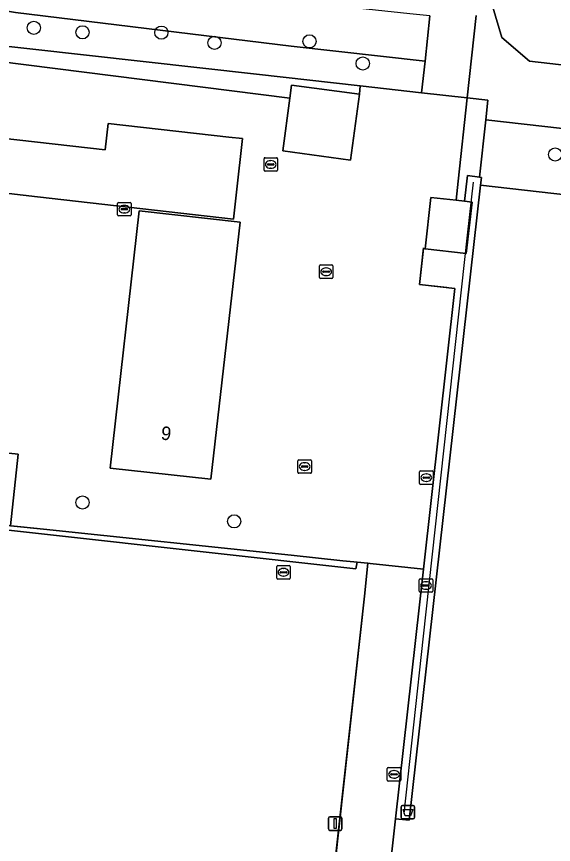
# Model space of a CAD drawing. Extents: x 162510 to 163918, y 388494 to 389774.
# Drawn here: x 162979.6 to 163019.4, y 388786.2 to 388847.5 of the extents above; entities that cross this region are included whole.
import ezdxf

# ---------------------------------------------------------------- set-up
doc = ezdxf.new("R2010")
doc.units = 0
for name, color, linetype in [('IMGEO_Afvalbak', 7, 'Continuous'), ('IMGEO_Boom', 7, 'Continuous'), ('IMGEO_Grasland_agrarisch', 7, 'Continuous'), ('IMGEO_Grasland_overig', 7, 'Continuous'), ('IMGEO_Groenvoorziening', 7, 'Continuous'), ('IMGEO_Hek', 7, 'Continuous'), ('IMGEO_Houtwal', 7, 'Continuous'), ('IMGEO_Kolk', 7, 'Continuous'), ('IMGEO_Lichtmast', 7, 'Continuous'), ('IMGEO_Loofbos', 7, 'Continuous'), ('IMGEO_Pand', 7, 'Continuous'), ('IMGEO_Pand_nummerreeks', 7, 'Continuous'), ('IMGEO_Rijbaan_lokaal_open', 7, 'Continuous'), ('IMGEO_Rioolput', 7, 'Continuous'), ('IMGEO_Terreindeel_open', 7, 'Continuous'), ('IMGEO_Voetpad_onverhard', 7, 'Continuous'), ('IMGEO_Voetpad_open', 7, 'Continuous')]:
    doc.layers.add(name, color=color, linetype=linetype)

msp = doc.modelspace()

# ---------------------------------------------------------------- linework, layer by layer
at = {"layer": 'IMGEO_Afvalbak'}
for p, q in [((163008.161, 388788.14), (163008.161, 388788.94)), ((163008.161, 388788.94), (163008.161, 388788.14)), ((163008.261, 388789.04), (163009.051, 388789.04)), ((163009.051, 388789.04), (163008.261, 388789.04)), ((163009.151, 388788.94), (163009.151, 388788.14)), ((163009.151, 388788.14), (163009.151, 388788.94)), ((163009.051, 388788.04), (163008.261, 388788.04)), ((163008.261, 388788.04), (163009.051, 388788.04))]:
    msp.add_line(p, q, dxfattribs=at)
msp.add_lwpolyline([(163008.304, 388788.754), (163009.008, 388788.754), (163008.859, 388788.284), (163008.453, 388788.284), (163008.304, 388788.754)], dxfattribs=at)
for centre, start, end in [((163008.261, 388788.94), 90, 180), ((163008.261, 388788.94), 90, 180), ((163009.051, 388788.94), 0, 90), ((163009.051, 388788.94), 360, 90), ((163008.261, 388788.14), 180, 270), ((163008.261, 388788.14), 180, 270), ((163009.051, 388788.14), 270, 0), ((163009.051, 388788.14), 270, 0)]:
    msp.add_arc(centre, 0.1, start, end, dxfattribs=at)
at = {"layer": 'IMGEO_Boom'}
for centre in [(162980.923, 388846.675), (162984.528, 388846.341), (162990.381, 388846.315), (162994.318, 388845.562), (163001.362, 388845.667), (163005.307, 388844.026), (163019.568, 388837.287), (162984.528, 388811.498), (162995.773, 388810.096)]:
    msp.add_circle(centre, 0.489, dxfattribs=at)
at = {"layer": 'IMGEO_Grasland_agrarisch'}
msp.add_lwpolyline([(163027.072, 388891.477), (162993.528, 388895.29), (162992.032, 388880.136), (162993.087, 388878.077), (162993.953, 388876.52), (163000.591, 388868.452), (163013.337, 388853.633), (163015.612, 388845.965), (163017.673, 388844.204), (163104.81, 388834.206)], dxfattribs=at)
at = {"layer": 'IMGEO_Grasland_overig'}
msp.add_lwpolyline([(162774.839, 389000), (162777.135, 388956.129), (162778.831, 388954.663), (162779.955, 388953.691), (162780.453, 388946.501), (162790.547, 388873.945), (162879.792, 388864.663), (162979.559, 388847.808), (163000, 388845.318), (163009.923, 388844.191), (163010.289, 388847.555), (163008.804, 388847.711), (163000, 388848.639), (162973.828, 388852.079)], dxfattribs=at)
at = {"layer": 'IMGEO_Groenvoorziening'}
for points in [[(162981.636, 388809.507), (162979.197, 388809.763), (162972.476, 388810.468), (162868.327, 388822.062), (162872.602, 388861.371), (162799.078, 388869.538), (162799.041, 388869.269), (162871.559, 388861.161), (162872.238, 388860.105), (162867.846, 388821.822), (163004.798, 388806.577), (163004.9, 388807.069), (163004.637, 388807.096), (163003.824, 388807.181), (163000, 388807.582)], [(163119.889, 388822.986), (163014.044, 388835.011), (163008.756, 388787.944), (163007.737, 388788.054), (163003.56, 388750.47), (163004.604, 388750.347), (163004.147, 388746.215), (163003.255, 388738.16), (163001.722, 388724.299), (163001.611, 388723.299), (163001.32, 388723.33), (163000, 388710.953), (162999.089, 388702.41), (163000, 388702.312), (163104.95, 388690.968), (163111.679, 388750)]]:
    msp.add_lwpolyline(points, close=True, dxfattribs=at)
for points in [[(163000, 388755.61), (163005.427, 388804.551), (163005.689, 388806.988), (163004.9, 388807.069), (163004.798, 388806.577), (162867.846, 388821.822), (162872.238, 388860.105), (162871.559, 388861.161), (162799.041, 388869.269), (162798.244, 388863.435), (162742.465, 388857.66)], [(162868.327, 388822.062), (162972.476, 388810.468), (162979.197, 388809.763), (162979.755, 388815.086), (162971.737, 388815.952), (162971.669, 388815.631), (162960.815, 388816.865), (162949.322, 388818.171), (162949.815, 388823.253), (162949.289, 388823.333), (162949.563, 388825.794), (162943.388, 388826.504), (162944.053, 388832.282), (162942.876, 388832.417), (162944.568, 388847.133), (162951.853, 388846.32), (162951.985, 388847.505), (162999.905, 388841.465), (163000.034, 388842.427), (163005.06, 388841.755), (163005.122, 388842.376), (162997.437, 388843.236), (162976.404, 388845.59), (162888.818, 388859.069)]]:
    msp.add_lwpolyline(points, dxfattribs=at)
at = {"layer": 'IMGEO_Hek'}
for points in [[(163000, 388845.318), (162979.559, 388847.808), (162879.792, 388864.663)], [(162888.818, 388859.069), (162976.404, 388845.59), (162997.437, 388843.236)], [(163000, 388845.318), (163009.923, 388844.191)], [(162997.437, 388843.236), (163005.122, 388842.376), (163009.67, 388841.867)], [(162999.381, 388837.545), (162999.905, 388841.465), (163000.034, 388842.427)], [(163000.034, 388842.427), (163005.06, 388841.755)], [(163005.06, 388841.755), (163004.407, 388836.873)], [(163009.67, 388841.867), (163013.046, 388841.484)], [(163013.046, 388841.484), (163014.583, 388841.309), (163014.422, 388839.85)], [(163014.422, 388839.85), (163013.951, 388835.598)], [(163004.407, 388836.873), (162999.381, 388837.545)], [(163008.368, 388788.444), (163009.813, 388801.599), (163013.076, 388831.3), (163013.51, 388835.244)], [(163014.044, 388835.011), (163119.889, 388822.986), (163111.679, 388750)], [(163011.529, 388827.418), (163009.522, 388827.661), (163009.819, 388830.371)], [(162981.636, 388809.507), (162972.476, 388810.468)], [(163003.824, 388807.181), (163000, 388807.582), (162981.636, 388809.507)], [(163005.689, 388806.988), (163005.427, 388804.551), (162995.492, 388714.399)], [(163004.637, 388807.096), (163003.824, 388807.181)], [(163004.637, 388807.096), (163004.9, 388807.069)], [(163004.9, 388807.069), (163005.689, 388806.988), (163005.868, 388806.969)], [(163009.285, 388806.615), (163005.868, 388806.969)]]:
    msp.add_lwpolyline(points, dxfattribs=at)
at = {"layer": 'IMGEO_Houtwal'}
msp.add_lwpolyline([(162879.792, 388864.663), (162790.547, 388873.945), (162789.747, 388873.272), (162788.349, 388873.034), (162788.737, 388870.608), (162799.078, 388869.538), (162872.602, 388861.371), (162879.687, 388860.474), (162888.818, 388859.069), (162976.404, 388845.59), (162997.437, 388843.236), (163005.122, 388842.376), (163009.67, 388841.867), (163009.923, 388844.191), (163000, 388845.318), (162979.559, 388847.808)], close=True, dxfattribs=at)
at = {"layer": 'IMGEO_Kolk'}
for p, q in [((162998.062, 388837.048), (162998.914, 388837.048)), ((162997.987, 388836.122), (162997.987, 388836.974)), ((162998.246, 388836.542), (162998.246, 388836.554)), ((162998.684, 388836.505), (162998.286, 388836.505)), ((162998.289, 388836.591), (162998.687, 388836.591)), ((162998.475, 388836.828), (162998.5, 388836.828)), ((162998.73, 388836.554), (162998.73, 388836.542)), ((162998.988, 388836.974), (162998.988, 388836.122)), ((162998.914, 388836.048), (162998.062, 388836.048)), ((162998.498, 388836.268), (162998.473, 388836.268)), ((162987.135, 388832.805), (162987.135, 388833.657)), ((162987.21, 388833.731), (162988.062, 388833.731)), ((162987.623, 388833.511), (162987.648, 388833.511)), ((162988.136, 388833.657), (162988.136, 388832.805)), ((162988.062, 388832.731), (162987.21, 388832.731)), ((162987.394, 388833.225), (162987.394, 388833.237)), ((162987.832, 388833.188), (162987.434, 388833.188)), ((162987.437, 388833.274), (162987.835, 388833.274)), ((162987.646, 388832.951), (162987.621, 388832.951)), ((162987.878, 388833.237), (162987.878, 388833.225)), ((163002.092, 388828.171), (163002.092, 388829.023)), ((163002.167, 388829.097), (163003.019, 388829.097)), ((163003.093, 388829.023), (163003.093, 388828.171)), ((163002.351, 388828.591), (163002.351, 388828.603)), ((163002.789, 388828.554), (163002.391, 388828.554)), ((163002.394, 388828.64), (163002.792, 388828.64)), ((163002.58, 388828.877), (163002.605, 388828.877)), ((163002.835, 388828.603), (163002.835, 388828.591)), ((163003.019, 388828.097), (163002.167, 388828.097)), ((163002.603, 388828.317), (163002.578, 388828.317)), ((163000.505, 388813.732), (163000.505, 388814.584)), ((163000.58, 388814.658), (163001.432, 388814.658)), ((163000.993, 388814.438), (163001.018, 388814.438)), ((163001.506, 388814.584), (163001.506, 388813.732)), ((163000.764, 388814.152), (163000.764, 388814.164)), ((163001.202, 388814.115), (163000.804, 388814.115)), ((163000.807, 388814.201), (163001.205, 388814.201)), ((163001.016, 388813.878), (163000.991, 388813.878)), ((163001.248, 388814.164), (163001.248, 388814.152)), ((163009.516, 388812.91), (163009.516, 388813.762)), ((163009.591, 388813.836), (163010.443, 388813.836)), ((163010.517, 388813.762), (163010.517, 388812.91)), ((163001.432, 388813.658), (163000.58, 388813.658)), ((163009.775, 388813.33), (163009.775, 388813.342)), ((163010.213, 388813.293), (163009.815, 388813.293)), ((163009.818, 388813.379), (163010.216, 388813.379)), ((163010.004, 388813.616), (163010.029, 388813.616)), ((163010.259, 388813.342), (163010.259, 388813.33)), ((163010.443, 388812.836), (163009.591, 388812.836)), ((163010.027, 388813.056), (163010.002, 388813.056)), ((163007.128, 388790.922), (163007.128, 388791.774)), ((163007.203, 388791.848), (163008.055, 388791.848)), ((163007.616, 388791.628), (163007.641, 388791.628)), ((163008.129, 388791.774), (163008.129, 388790.922)), ((163007.387, 388791.342), (163007.387, 388791.354)), ((163007.825, 388791.305), (163007.427, 388791.305)), ((163007.43, 388791.391), (163007.828, 388791.391)), ((163007.639, 388791.068), (163007.614, 388791.068)), ((163007.871, 388791.354), (163007.871, 388791.342)), ((163008.055, 388790.848), (163007.203, 388790.848))]:
    msp.add_line(p, q, dxfattribs=at)
for points in [[(162998.062, 388837.048), (162998.914, 388837.048)], [(162997.987, 388836.122), (162997.987, 388836.974)], [(162998.988, 388836.974), (162998.988, 388836.122)], [(162998.914, 388836.048), (162998.062, 388836.048)], [(162987.135, 388832.805), (162987.135, 388833.657)], [(162987.21, 388833.731), (162988.062, 388833.731)], [(162988.136, 388833.657), (162988.136, 388832.805)], [(162988.062, 388832.731), (162987.21, 388832.731)], [(163002.092, 388828.171), (163002.092, 388829.023)], [(163002.167, 388829.097), (163003.019, 388829.097)], [(163003.093, 388829.023), (163003.093, 388828.171)], [(163003.019, 388828.097), (163002.167, 388828.097)], [(163000.505, 388813.732), (163000.505, 388814.584)], [(163000.58, 388814.658), (163001.432, 388814.658)], [(163001.506, 388814.584), (163001.506, 388813.732)], [(163009.516, 388812.91), (163009.516, 388813.762)], [(163009.591, 388813.836), (163010.443, 388813.836)], [(163010.517, 388813.762), (163010.517, 388812.91)], [(163001.432, 388813.658), (163000.58, 388813.658)], [(163010.443, 388812.836), (163009.591, 388812.836)], [(163007.128, 388790.922), (163007.128, 388791.774)], [(163007.203, 388791.848), (163008.055, 388791.848)], [(163008.129, 388791.774), (163008.129, 388790.922)], [(163008.055, 388790.848), (163007.203, 388790.848)]]:
    msp.add_lwpolyline(points, dxfattribs=at)
for centre, radius, start, end in [((162998.064, 388836.972), 0.0765, 91.55205, 178.44795), ((162998.064, 388836.972), 0.0765, 91.55205, 178.44795), ((162998.912, 388836.972), 0.0765, 1.55205, 88.44795), ((162998.912, 388836.972), 0.0765, 1.55205, 88.44795), ((162998.286, 388836.551), 0.0403, 85.87752, 175.75265), ((162998.283, 388836.541), 0.0366, 178.93798, 274.71019), ((162998.687, 388836.548), 0.043, 264.86636, 352.45326), ((162998.691, 388836.553), 0.0386, 1.73085, 96.63898), ((162998.064, 388836.124), 0.0765, 181.55205, 268.44795), ((162998.064, 388836.124), 0.0765, 181.55205, 268.44795), ((162998.912, 388836.124), 0.0765, 271.55205, 358.44795), ((162998.912, 388836.124), 0.0765, 271.55205, 358.44795), ((162987.212, 388833.655), 0.0765, 91.55205, 178.44795), ((162987.212, 388833.655), 0.0765, 91.55205, 178.44795), ((162988.06, 388833.655), 0.0765, 1.55205, 88.44795), ((162988.06, 388833.655), 0.0765, 1.55205, 88.44795), ((162987.212, 388832.807), 0.0765, 181.55205, 268.44795), ((162987.212, 388832.807), 0.0765, 181.55205, 268.44795), ((162987.434, 388833.234), 0.0403, 85.87752, 175.75265), ((162987.431, 388833.224), 0.0366, 178.93798, 274.71019), ((162987.835, 388833.231), 0.043, 264.86636, 352.45326), ((162987.839, 388833.236), 0.0386, 1.73085, 96.63898), ((162988.06, 388832.807), 0.0765, 271.55205, 358.44795), ((162988.06, 388832.807), 0.0765, 271.55205, 358.44795), ((163002.169, 388829.021), 0.0765, 91.55205, 178.44795), ((163002.169, 388829.021), 0.0765, 91.55205, 178.44795), ((163003.017, 388829.021), 0.0765, 1.55205, 88.44795), ((163003.017, 388829.021), 0.0765, 1.55205, 88.44795), ((163002.391, 388828.6), 0.0403, 85.87752, 175.75265), ((163002.388, 388828.59), 0.0366, 178.93798, 274.71019), ((163002.792, 388828.597), 0.043, 264.86636, 352.45326), ((163002.796, 388828.602), 0.0386, 1.73085, 96.63898), ((163002.169, 388828.173), 0.0765, 181.55205, 268.44795), ((163002.169, 388828.173), 0.0765, 181.55205, 268.44795), ((163003.017, 388828.173), 0.0765, 271.55205, 358.44795), ((163003.017, 388828.173), 0.0765, 271.55205, 358.44795), ((163000.582, 388814.582), 0.0765, 91.55205, 178.44795), ((163000.582, 388814.582), 0.0765, 91.55205, 178.44795), ((163001.43, 388814.582), 0.0765, 1.55205, 88.44795), ((163001.43, 388814.582), 0.0765, 1.55205, 88.44795), ((163000.582, 388813.734), 0.0765, 181.55205, 268.44795), ((163000.582, 388813.734), 0.0765, 181.55205, 268.44795), ((163000.804, 388814.161), 0.0403, 85.87752, 175.75265), ((163000.801, 388814.151), 0.0366, 178.93798, 274.71019), ((163001.205, 388814.158), 0.043, 264.86636, 352.45326), ((163001.209, 388814.163), 0.0386, 1.73085, 96.63898), ((163001.43, 388813.734), 0.0765, 271.55205, 358.44795), ((163001.43, 388813.734), 0.0765, 271.55205, 358.44795), ((163009.593, 388813.76), 0.0765, 91.55205, 178.44795), ((163009.593, 388813.76), 0.0765, 91.55205, 178.44795), ((163010.441, 388813.76), 0.0765, 1.55205, 88.44795), ((163010.441, 388813.76), 0.0765, 1.55205, 88.44795), ((163009.815, 388813.339), 0.0403, 85.87752, 175.75265), ((163009.812, 388813.329), 0.0366, 178.93798, 274.71019), ((163010.216, 388813.336), 0.043, 264.86636, 352.45326), ((163010.22, 388813.341), 0.0386, 1.73085, 96.63898), ((163009.593, 388812.912), 0.0765, 181.55205, 268.44795), ((163009.593, 388812.912), 0.0765, 181.55205, 268.44795), ((163010.441, 388812.912), 0.0765, 271.55205, 358.44795), ((163010.441, 388812.912), 0.0765, 271.55205, 358.44795), ((163007.205, 388791.772), 0.0765, 91.55205, 178.44795), ((163007.205, 388791.772), 0.0765, 91.55205, 178.44795), ((163008.053, 388791.772), 0.0765, 1.55205, 88.44795), ((163008.053, 388791.772), 0.0765, 1.55205, 88.44795), ((163007.427, 388791.351), 0.0403, 85.87752, 175.75265), ((163007.424, 388791.341), 0.0366, 178.93798, 274.71019), ((163007.828, 388791.348), 0.043, 264.86636, 352.45326), ((163007.832, 388791.353), 0.0386, 1.73085, 96.63898), ((163007.205, 388790.924), 0.0765, 181.55205, 268.44795), ((163007.205, 388790.924), 0.0765, 181.55205, 268.44795), ((163008.053, 388790.924), 0.0765, 271.55205, 358.44795), ((163008.053, 388790.924), 0.0765, 271.55205, 358.44795)]:
    msp.add_arc(centre, radius, start, end, dxfattribs=at)
for centre, major_axis, ratio, start_param, end_param in [((162998.474, 388836.548), (-0.387, 0.002), 0.722429, 4.712389, 7.853982), ((162998.499, 388836.548), (-0.39, 0.002), 0.717154, 1.570796, 4.712389), ((162987.622, 388833.231), (-0.387, 0.002), 0.722429, 4.712389, 7.853982), ((162987.647, 388833.231), (-0.39, 0.002), 0.717154, 1.570796, 4.712389), ((163002.579, 388828.597), (-0.387, 0.002), 0.722429, 4.712389, 7.853982), ((163002.604, 388828.597), (-0.39, 0.002), 0.717154, 1.570796, 4.712389), ((163000.992, 388814.158), (-0.387, 0.002), 0.722429, 4.712389, 7.853982), ((163001.017, 388814.158), (-0.39, 0.002), 0.717154, 1.570796, 4.712389), ((163010.003, 388813.336), (-0.387, 0.002), 0.722429, 4.712389, 7.853982), ((163010.028, 388813.336), (-0.39, 0.002), 0.717154, 1.570796, 4.712389), ((163007.615, 388791.348), (-0.387, 0.002), 0.722429, 4.712389, 7.853982), ((163007.64, 388791.348), (-0.39, 0.002), 0.717154, 1.570796, 4.712389)]:
    msp.add_ellipse(centre, major_axis=major_axis, ratio=ratio, start_param=start_param, end_param=end_param, dxfattribs=at)
at = {"layer": 'IMGEO_Lichtmast'}
for p, q in [((163002.773, 388787.298), (163002.773, 388788.098)), ((163002.773, 388788.098), (163002.773, 388787.298)), ((163002.873, 388788.198), (163003.663, 388788.198)), ((163003.663, 388788.198), (163002.873, 388788.198)), ((163003.763, 388788.098), (163003.763, 388787.298)), ((163003.763, 388787.298), (163003.763, 388788.098)), ((163003.663, 388787.198), (163002.873, 388787.198)), ((163002.873, 388787.198), (163003.663, 388787.198))]:
    msp.add_line(p, q, dxfattribs=at)
msp.add_lwpolyline([(163003.193, 388788.073), (163003.343, 388788.073), (163003.343, 388787.323), (163003.193, 388787.323), (163003.193, 388788.073)], dxfattribs=at)
for centre, start, end in [((163002.873, 388788.098), 90, 180), ((163002.873, 388788.098), 90, 180), ((163003.663, 388788.098), 0, 90), ((163003.663, 388788.098), 360, 90), ((163002.873, 388787.298), 180, 270), ((163002.873, 388787.298), 180, 270), ((163003.663, 388787.298), 270, 0), ((163003.663, 388787.298), 270, 0)]:
    msp.add_arc(centre, 0.1, start, end, dxfattribs=at)
at = {"layer": 'IMGEO_Loofbos'}
msp.add_lwpolyline([(163124.377, 388827.421), (163014.422, 388839.85), (163013.951, 388835.598), (163014.107, 388835.576), (163014.044, 388835.011), (163119.889, 388822.986)], dxfattribs=at)
at = {"layer": 'IMGEO_Pand'}
for points in [[(163012.85, 388833.817), (163012.226, 388833.889), (163010.366, 388834.104), (163009.927, 388830.299), (163012.968, 388829.949), (163013.407, 388833.753)], [(162996.215, 388832.282), (162988.731, 388833.119), (162986.579, 388814.028), (162994.057, 388813.226)]]:
    msp.add_lwpolyline(points, close=True, dxfattribs=at)
at = {"layer": 'IMGEO_Rijbaan_lokaal_open'}
msp.add_lwpolyline([(163010.289, 388847.555), (163009.923, 388844.191), (163009.67, 388841.867), (163013.046, 388841.484), (163013.705, 388847.595)], dxfattribs=at)
at = {"layer": 'IMGEO_Rioolput'}
for p, q in [((162998.933, 388805.896), (162998.933, 388806.748)), ((162999.008, 388806.822), (162999.86, 388806.822)), ((162999.192, 388806.316), (162999.192, 388806.328)), ((162999.235, 388806.365), (162999.633, 388806.365)), ((162999.421, 388806.602), (162999.446, 388806.602)), ((162999.676, 388806.328), (162999.676, 388806.316)), ((162999.934, 388806.748), (162999.934, 388805.896)), ((162999.86, 388805.822), (162999.008, 388805.822)), ((162999.63, 388806.279), (162999.232, 388806.279)), ((162999.444, 388806.042), (162999.419, 388806.042)), ((163009.499, 388804.914), (163009.499, 388805.766)), ((163009.574, 388805.84), (163010.426, 388805.84)), ((163010.5, 388805.766), (163010.5, 388804.914)), ((163009.758, 388805.334), (163009.758, 388805.346)), ((163010.196, 388805.297), (163009.798, 388805.297)), ((163009.801, 388805.383), (163010.199, 388805.383)), ((163009.987, 388805.62), (163010.012, 388805.62)), ((163010.242, 388805.346), (163010.242, 388805.334)), ((163010.426, 388804.84), (163009.574, 388804.84)), ((163010.01, 388805.06), (163009.985, 388805.06))]:
    msp.add_line(p, q, dxfattribs=at)
for points in [[(162998.933, 388805.896), (162998.933, 388806.748)], [(162999.008, 388806.822), (162999.86, 388806.822)], [(162999.934, 388806.748), (162999.934, 388805.896)], [(162999.86, 388805.822), (162999.008, 388805.822)], [(163009.499, 388804.914), (163009.499, 388805.766)], [(163009.574, 388805.84), (163010.426, 388805.84)], [(163010.5, 388805.766), (163010.5, 388804.914)], [(163010.426, 388804.84), (163009.574, 388804.84)]]:
    msp.add_lwpolyline(points, dxfattribs=at)
for centre, radius, start, end in [((162999.01, 388806.746), 0.0765, 91.55205, 178.44795), ((162999.01, 388806.746), 0.0765, 91.55205, 178.44795), ((162999.232, 388806.325), 0.0403, 85.87752, 175.75265), ((162999.637, 388806.327), 0.0386, 1.73085, 96.63898), ((162999.858, 388806.746), 0.0765, 1.55205, 88.44795), ((162999.858, 388806.746), 0.0765, 1.55205, 88.44795), ((162999.01, 388805.898), 0.0765, 181.55205, 268.44795), ((162999.01, 388805.898), 0.0765, 181.55205, 268.44795), ((162999.229, 388806.315), 0.0366, 178.93798, 274.71019), ((162999.633, 388806.322), 0.043, 264.86636, 352.45326), ((162999.858, 388805.898), 0.0765, 271.55205, 358.44795), ((162999.858, 388805.898), 0.0765, 271.55205, 358.44795), ((163009.576, 388805.764), 0.0765, 91.55205, 178.44795), ((163009.576, 388805.764), 0.0765, 91.55205, 178.44795), ((163010.424, 388805.764), 0.0765, 1.55205, 88.44795), ((163010.424, 388805.764), 0.0765, 1.55205, 88.44795), ((163009.798, 388805.343), 0.0403, 85.87752, 175.75265), ((163009.795, 388805.333), 0.0366, 178.93798, 274.71019), ((163010.199, 388805.34), 0.043, 264.86636, 352.45326), ((163010.203, 388805.345), 0.0386, 1.73085, 96.63898), ((163009.576, 388804.916), 0.0765, 181.55205, 268.44795), ((163009.576, 388804.916), 0.0765, 181.55205, 268.44795), ((163010.424, 388804.916), 0.0765, 271.55205, 358.44795), ((163010.424, 388804.916), 0.0765, 271.55205, 358.44795)]:
    msp.add_arc(centre, radius, start, end, dxfattribs=at)
for centre, major_axis, ratio, start_param, end_param in [((162999.42, 388806.322), (-0.387, 0.002), 0.722429, 4.712389, 7.853982), ((162999.445, 388806.322), (-0.39, 0.002), 0.717154, 1.570796, 4.712389), ((163009.986, 388805.34), (-0.387, 0.002), 0.722429, 4.712389, 7.853982), ((163010.011, 388805.34), (-0.39, 0.002), 0.717154, 1.570796, 4.712389)]:
    msp.add_ellipse(centre, major_axis=major_axis, ratio=ratio, start_param=start_param, end_param=end_param, dxfattribs=at)
at = {"layer": 'IMGEO_Terreindeel_open'}
msp.add_lwpolyline([(163005.06, 388841.755), (163000.034, 388842.427), (162999.905, 388841.465), (162999.381, 388837.545), (163004.407, 388836.873)], close=True, dxfattribs=at)
at = {"layer": 'IMGEO_Voetpad_onverhard'}
for points in [[(163122.744, 388835.249), (163120.935, 388841.597), (163121.936, 388842.227), (163115.86, 388872.571), (163115.598, 388873.88), (163111.758, 388891.053), (163111.658, 388892.011), (163103.594, 388890.933), (163113.388, 388833.94), (163104.81, 388834.206), (163017.673, 388844.204), (163015.612, 388845.965), (163013.337, 388853.633), (163000.591, 388868.452), (162993.953, 388876.52), (162993.087, 388878.077), (162992.032, 388880.136)], [(163013.705, 388847.595), (163013.046, 388841.484), (163014.583, 388841.309), (163014.422, 388839.85), (163124.377, 388827.421)]]:
    msp.add_lwpolyline(points, dxfattribs=at)
at = {"layer": 'IMGEO_Voetpad_open'}
for points in [[(162971.737, 388815.952), (162979.755, 388815.086), (162979.197, 388809.763), (162981.636, 388809.507), (163000, 388807.582), (163003.824, 388807.181), (163004.637, 388807.096), (163004.9, 388807.069), (163005.689, 388806.988), (163005.868, 388806.969), (163009.805, 388806.561), (163012.127, 388827.346), (163009.522, 388827.661), (163009.813, 388830.312), (163009.927, 388830.299), (163010.366, 388834.104), (163012.226, 388833.889), (163012.38, 388835.312), (163013.046, 388841.484), (163009.67, 388841.867), (163005.122, 388842.376), (163005.06, 388841.755), (163004.407, 388836.873), (162999.381, 388837.545), (162999.905, 388841.465), (162951.985, 388847.505)], [(163003.56, 388750.47), (163007.737, 388788.054), (163009.805, 388806.561), (163005.868, 388806.969), (163005.689, 388806.988), (163005.427, 388804.551), (163000, 388755.61)]]:
    msp.add_lwpolyline(points, dxfattribs=at)
for points in [[(162981.195, 388834.159), (162969.276, 388835.519), (162952.006, 388837.489), (162952.454, 388841.455), (162959.136, 388840.698), (162986.214, 388837.63), (162986.443, 388839.59), (162995.379, 388838.578), (162996.391, 388838.463), (162995.94, 388834.483), (162995.716, 388832.502)], [(162995.94, 388834.483), (162996.391, 388838.463), (162995.379, 388838.578), (162986.443, 388839.59), (162986.214, 388837.63), (162959.136, 388840.698), (162952.454, 388841.455), (162952.006, 388837.489), (162969.276, 388835.519), (162981.195, 388834.159), (162995.716, 388832.502)], [(163014.422, 388839.85), (163014.583, 388841.309), (163013.046, 388841.484), (163012.38, 388835.312), (163012.226, 388833.889), (163012.85, 388833.817), (163013.063, 388835.727), (163013.951, 388835.598)], [(163014.044, 388835.011), (163014.107, 388835.576), (163013.951, 388835.598), (163013.063, 388835.727), (163012.85, 388833.817), (163013.407, 388833.753), (163012.968, 388829.949), (163009.927, 388830.299), (163009.813, 388830.312), (163009.522, 388827.661), (163012.127, 388827.346), (163009.805, 388806.561), (163007.737, 388788.054), (163008.756, 388787.944)], [(162988.731, 388833.119), (162996.215, 388832.282), (162994.057, 388813.226), (162986.579, 388814.028)]]:
    msp.add_lwpolyline(points, close=True, dxfattribs=at)

# ---------------------------------------------------------------- texts
at = {"layer": 'IMGEO_Pand_nummerreeks'}
msp.add_text('9', height=1, rotation=353.87854, dxfattribs=at).set_placement((162990.312, 388816.162))

doc.saveas('drawing.dxf')
